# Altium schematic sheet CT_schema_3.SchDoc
size 357 x 214 mm
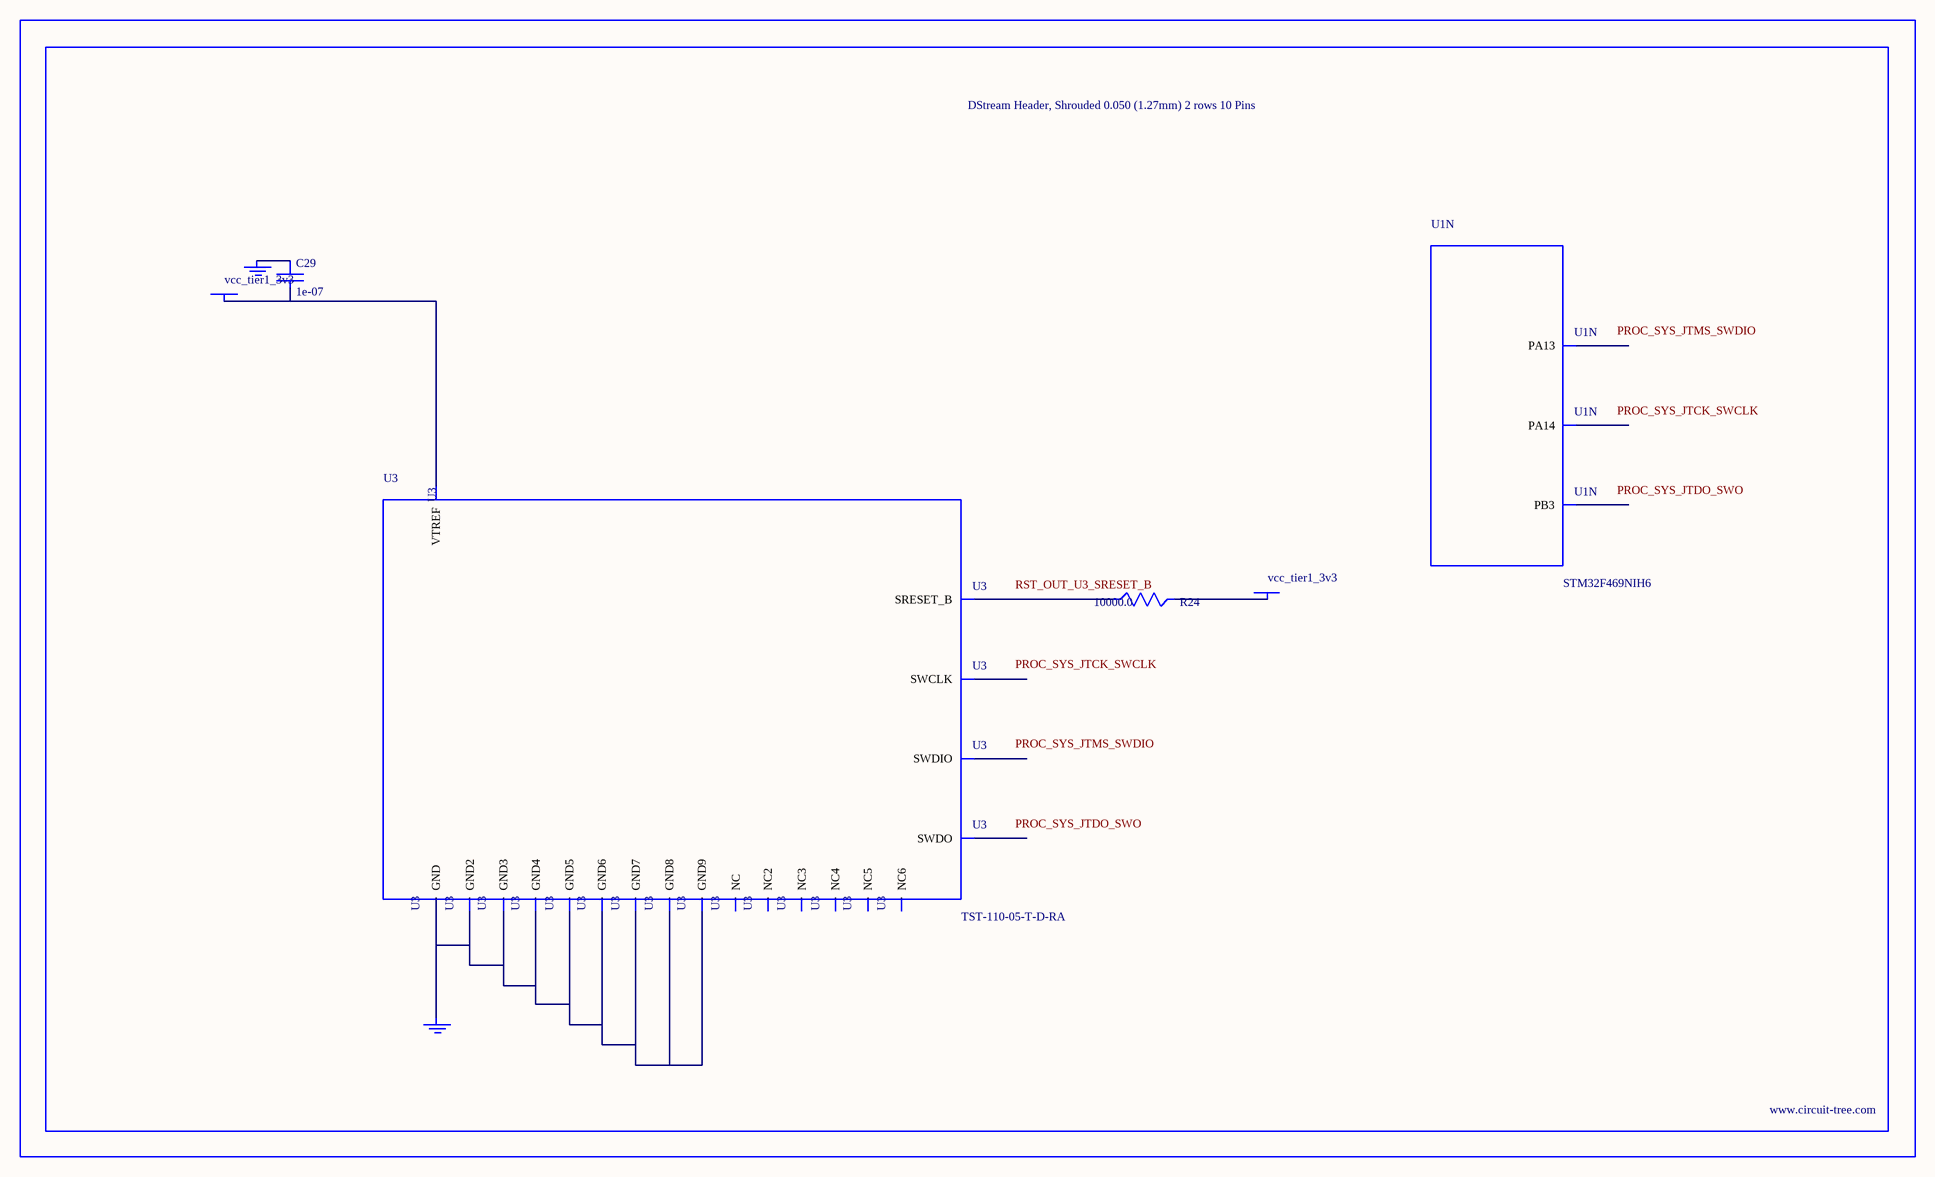
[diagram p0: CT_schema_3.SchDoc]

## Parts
BORDER2  (no value)
C29  1e-07  [C0402]
GND_INSTANCE_2_0  (no value)
GND_INSTANCE_2_1  (no value)
POWER_INSTANCE_2_0  vcc_tier1_3v3
POWER_INSTANCE_2_1  vcc_tier1_3v3
R24  10000.0  [R0603]
U1  STM32F469NIH6  [TFBGA216]  (part N of 17)
U3  TST-110-05-T-D-RA  [TST-110-05-T-D-RA]

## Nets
NetC29_1: C29.1 GND_INSTANCE_2_0.0(GND)
NetC29_2: C29.2 POWER_INSTANCE_2_0.0(PWR) U3.1(VTREF)
NetGND_INSTANCE_2_1_0: GND_INSTANCE_2_1.0(GND) U3.4(GND) U3.6(GND2) U3.8(GND3) U3.10(GND4) U3.12(GND5) U3.14(GND6) U3.16(GND7) U3.18(GND8) U3.20(GND9)
NetPOWER_INSTANCE_2_1_0: POWER_INSTANCE_2_1.0(PWR) R24.2
NetR24_1: R24.1 U3.15(SRESET_B)

Not connected (* = marked no-connect by the designer): U1 A10(PB3) A14(PA14) A15(PA13); U3 2(NC) 3(NC2) 5(NC3) 7(SWDIO) 9(SWCLK) 11(NC4) 13(SWDO) 17(NC5) 19(NC6)

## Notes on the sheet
- Labels drawn without touching a wire or pin: PROC_SYS_JTCK_SWCLK, PROC_SYS_JTDO_SWO, PROC_SYS_JTMS_SWDIO, RST_OUT_U3_SRESET_B

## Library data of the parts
BORDER2 = BORDER_PAGE2
C29 = C0402C104K3RACTU
GND_INSTANCE_2_0 GND_INSTANCE_2_1 = GND
POWER_INSTANCE_2_0 POWER_INSTANCE_2_1 = PWR
R24 = RC0603JR-0710KL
